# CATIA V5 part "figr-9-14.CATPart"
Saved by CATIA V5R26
Part number: Part2
Bounding box of the stored display mesh (mm): x -33.329 to 47.777, y -126.495 to 121.369, z -47.545 to 64.906
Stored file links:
  D:\_Deepak\CATIA\CATIA V5-6R2016_Deepak\Resources\Part files\Partfiles\c09_catia_v5_6r2016_prt\figr-9-14.CATPart
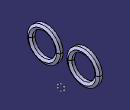
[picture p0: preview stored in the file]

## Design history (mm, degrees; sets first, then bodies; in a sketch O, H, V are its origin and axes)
Body1 (main body)
  Sketch1 on yz-plane, origin (0, 0, 0), H (0, 1, 0), V (0, 0, 1)
    circle A1 centre (-70.2613, 8.6726) radius 37.6716
    circle A2 centre (65.3061, 8.6726) radius 37.5
    radius A2 = 37.5
    radius A1 = 37.6716
  Plane1: type Angle, RefPlane yz-plane, Direction Sketch1.V, Angle 10
  Plane2: type Offset, RefPlane Plane1, Offset 55
  Sketch2 on Plane2, origin (44.5537, 64.0556, 0), H (-0.1736, 0.9848, 0), V (0, 0, 1)
    point P1 (-10.3597, -23.8575)
    point P2 (-2.157, -28.5933)
    point P3 (-2.157, -19.1216)
    point P4 (-10.3597, -14.3858)
    point P5 (-18.5625, -19.1216)
    point P6 (-18.5625, -28.5933)
    point P7 (-10.3597, -33.3292)
    point P8 (-2.157, -23.8575)
    line L1 (-2.157, -28.5933) -> (-2.157, -19.1216)
    line L2 (-2.157, -19.1216) -> (-10.3597, -14.3858)
    line L3 (-10.3597, -14.3858) -> (-18.5625, -19.1216)
    line L4 (-18.5625, -19.1216) -> (-18.5625, -28.5933)
    line L5 (-18.5625, -28.5933) -> (-10.3597, -33.3292)
    line L6 (-10.3597, -33.3292) -> (-2.157, -28.5933)
    construction line L7 (-10.3597, -23.8575) -> (-2.157, -23.8575)
    construction circle A1 centre (-10.3597, -23.8575) radius 9.4717
    construction arc A2 centre (-18.5625, -28.5933) radius 9.4717 from (-18.5625, -19.1216) to (-10.3597, -33.3292) cw
    construction arc A3 centre (-2.157, -19.1216) radius 9.4717 from (-10.3597, -14.3858) to (-2.157, -28.5933) ccw
    horizontal: L7 H
    coincidence: A1 P2, A1 P3, A1 P4, A1 P5, A1 P6, A1 P7, A2 P1, A3 P1
    midpoint: P8 L1
    parallelism: L1 L4
  Rib1: profile Sketch2, centre curve Sketch1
